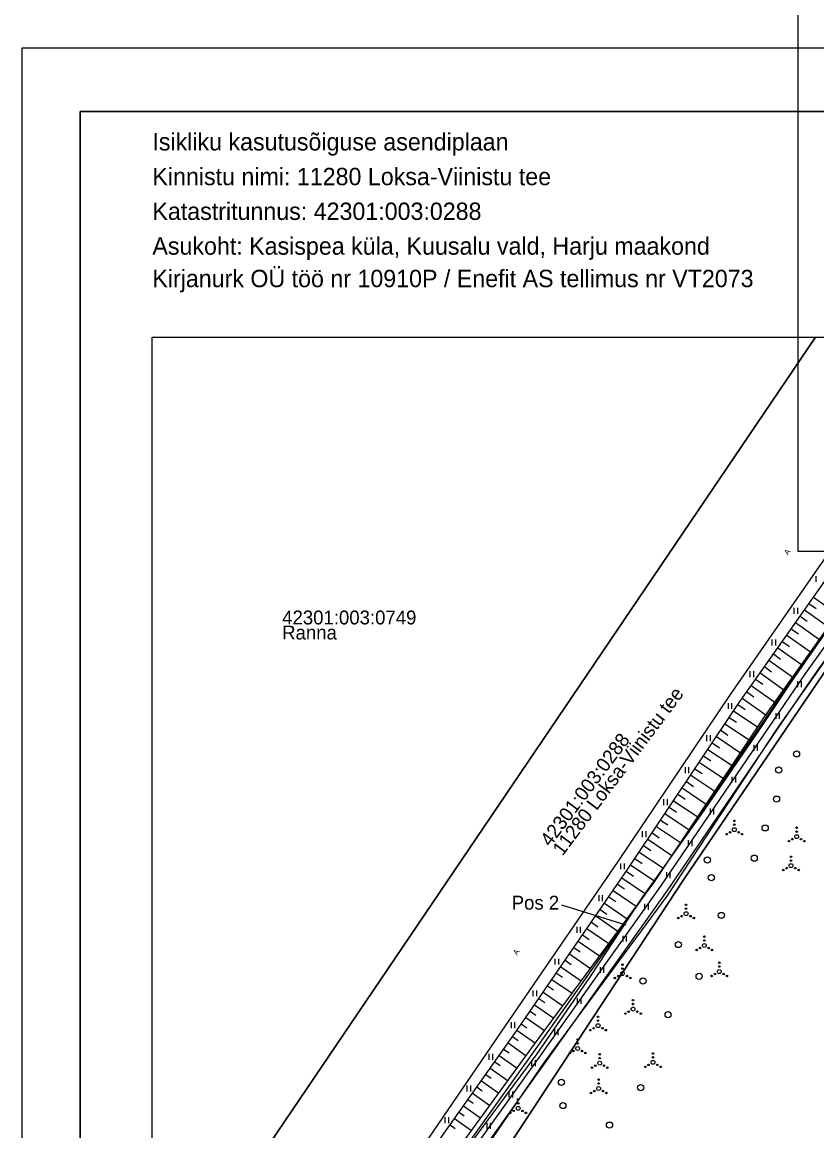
# Model space of a CAD drawing. Extents: x 599446 to 599962, y 6608194 to 6608886.
# Drawn here: x 599613.2 to 599716.2, y 6608430.8 to 6608574.4 of the extents above; entities that cross this region are included whole.
import ezdxf

# ---------------------------------------------------------------- set-up
doc = ezdxf.new("R2010")
doc.units = 0
for name, color, linetype in [('HALJASTUS', 7, 'Continuous'), ('KASUTUSALA', 7, 'Continuous'), ('MPKAABEL', 7, 'Continuous'), ('PIIR', 7, 'Continuous'), ('PR_SIDE', 7, 'Continuous'), ('RELJEEF', 7, 'Continuous'), ('TEE', 7, 'Continuous'), ('VORMISTUS_1', 7, 'Continuous'), ('VORMISTUS_2', 7, 'Continuous')]:
    doc.layers.add(name, color=color, linetype=linetype)

msp = doc.modelspace()

# ---------------------------------------------------------------- linework, layer by layer
at = {"layer": 'HALJASTUS'}
for p, q in [((599716.11, 6608502.67), (599716.11, 6608501.91)), ((599713.26, 6608498.56), (599713.26, 6608497.8)), ((599713.72, 6608498.56), (599713.72, 6608497.8)), ((599710.41, 6608494.45), (599710.41, 6608493.69)), ((599710.87, 6608494.45), (599710.87, 6608493.69)), ((599707.56, 6608490.34), (599707.56, 6608489.58)), ((599708.02, 6608490.34), (599708.02, 6608489.58)), ((599713.74, 6608489.04), (599713.74, 6608488.28)), ((599714.2, 6608489.04), (599714.2, 6608488.28)), ((599704.74, 6608486.22), (599704.74, 6608485.46)), ((599705.19, 6608486.22), (599705.19, 6608485.46)), ((599710.91, 6608484.92), (599710.91, 6608484.16)), ((599711.37, 6608484.92), (599711.37, 6608484.16)), ((599701.95, 6608482.07), (599701.95, 6608481.3)), ((599702.41, 6608482.07), (599702.41, 6608481.3)), ((599708.08, 6608480.8), (599708.08, 6608480.04)), ((599708.53, 6608480.8), (599708.53, 6608480.04)), ((599699.17, 6608477.91), (599699.17, 6608477.15)), ((599699.62, 6608477.91), (599699.62, 6608477.15)), ((599705.24, 6608476.68), (599705.24, 6608475.92)), ((599705.7, 6608476.68), (599705.7, 6608475.92)), ((599696.38, 6608473.76), (599696.38, 6608473)), ((599696.84, 6608473.76), (599696.84, 6608473)), ((599702.41, 6608472.57), (599702.41, 6608471.8)), ((599702.87, 6608472.57), (599702.87, 6608471.8)), ((599693.6, 6608469.61), (599693.6, 6608468.84)), ((599694.06, 6608469.61), (599694.06, 6608468.84)), ((599699.58, 6608468.45), (599699.58, 6608467.68)), ((599700.03, 6608468.45), (599700.03, 6608467.68)), ((599690.81, 6608465.46), (599690.81, 6608464.7)), ((599691.26, 6608465.46), (599691.26, 6608464.7)), ((599696.75, 6608464.33), (599696.75, 6608463.56)), ((599697.2, 6608464.33), (599697.2, 6608463.56)), ((599687.97, 6608461.34), (599687.97, 6608460.58)), ((599688.42, 6608461.34), (599688.42, 6608460.58)), ((599693.91, 6608460.21), (599693.91, 6608459.44)), ((599694.37, 6608460.21), (599694.37, 6608459.44)), ((599685.13, 6608457.23), (599685.13, 6608456.47)), ((599685.58, 6608457.23), (599685.58, 6608456.47)), ((599691.08, 6608456.09), (599691.08, 6608455.33)), ((599691.53, 6608456.09), (599691.53, 6608455.33)), ((599682.29, 6608453.11), (599682.29, 6608452.35)), ((599682.74, 6608453.11), (599682.74, 6608452.35)), ((599688.15, 6608452.03), (599688.15, 6608451.27)), ((599688.6, 6608452.03), (599688.6, 6608451.27)), ((599679.45, 6608449), (599679.45, 6608448.24)), ((599679.91, 6608449), (599679.91, 6608448.24)), ((599685.19, 6608448.01), (599685.19, 6608447.25)), ((599685.64, 6608448.01), (599685.64, 6608447.25)), ((599676.61, 6608444.88), (599676.61, 6608444.12)), ((599677.06, 6608444.88), (599677.06, 6608444.12)), ((599682.23, 6608443.98), (599682.23, 6608443.22)), ((599682.68, 6608443.98), (599682.68, 6608443.22)), ((599673.75, 6608440.78), (599673.75, 6608440.02)), ((599674.2, 6608440.78), (599674.2, 6608440.02)), ((599679.26, 6608439.95), (599679.26, 6608439.19)), ((599679.72, 6608439.95), (599679.72, 6608439.19)), ((599670.89, 6608436.68), (599670.89, 6608435.92)), ((599671.34, 6608436.68), (599671.34, 6608435.92)), ((599676.34, 6608435.9), (599676.34, 6608435.14)), ((599676.79, 6608435.9), (599676.79, 6608435.14)), ((599668.03, 6608432.58), (599668.03, 6608431.82)), ((599668.49, 6608432.58), (599668.49, 6608431.82)), ((599673.46, 6608431.81), (599673.46, 6608431.05)), ((599673.91, 6608431.81), (599673.91, 6608431.05))]:
    msp.add_line(p, q, dxfattribs=at)
msp.add_lwpolyline([(599677.55, 6608411.8), (599667.89, 6608408.84), (599664.05, 6608407.91), (599661.03, 6608410.48), (599668.3, 6608421.18), (599680.96, 6608439.71), (599696.95, 6608461.33), (599711.02, 6608482.75), (599725.24, 6608502.94), (599738.38, 6608523.58), (599745.5, 6608533.61)], dxfattribs=at)
for centre, radius in [((599713.62, 6608479.64), 0.4), ((599711.3, 6608477.55), 0.4), ((599711.02, 6608473.78), 0.4), ((599705.55, 6608470.97), 0.1), ((599704.98, 6608469.49), 0.1), ((599705.55, 6608469.82), 0.25), ((599705.55, 6608470.47), 0.1), ((599706.11, 6608469.49), 0.1), ((599709.55, 6608470.05), 0.4), ((599713.63, 6608470.07), 0.1), ((599713.63, 6608469.57), 0.1), ((599704.55, 6608469.24), 0.1), ((599706.55, 6608469.24), 0.1), ((599712.63, 6608468.34), 0.1), ((599713.07, 6608468.59), 0.1), ((599713.63, 6608468.92), 0.25), ((599714.2, 6608468.59), 0.1), ((599714.63, 6608468.34), 0.1), ((599702.06, 6608465.9), 0.4), ((599708.13, 6608466.13), 0.4), ((599712.9, 6608465.16), 0.25), ((599712.9, 6608466.31), 0.1), ((599712.9, 6608465.81), 0.1), ((599702.58, 6608463.6), 0.4), ((599711.9, 6608464.59), 0.1), ((599712.33, 6608464.84), 0.1), ((599713.46, 6608464.84), 0.1), ((599713.9, 6608464.59), 0.1), ((599699.3, 6608460.09), 0.1), ((599699.3, 6608459.59), 0.1), ((599698.3, 6608458.37), 0.1), ((599698.74, 6608458.62), 0.1), ((599699.3, 6608458.94), 0.25), ((599699.87, 6608458.62), 0.1), ((599700.3, 6608458.37), 0.1), ((599703.87, 6608458.71), 0.4), ((599698.31, 6608454.94), 0.4), ((599701.67, 6608455.97), 0.1), ((599701.67, 6608455.47), 0.1), ((599700.67, 6608454.24), 0.1), ((599701.11, 6608454.49), 0.1), ((599701.67, 6608454.82), 0.25), ((599702.24, 6608454.49), 0.1), ((599702.67, 6608454.24), 0.1), ((599691.06, 6608452.33), 0.1), ((599703.6, 6608452.59), 0.1), ((599690.5, 6608450.86), 0.1), ((599691.06, 6608451.18), 0.25), ((599691.06, 6608451.83), 0.1), ((599691.63, 6608450.86), 0.1), ((599700.99, 6608450.82), 0.4), ((599702.6, 6608450.87), 0.1), ((599703.04, 6608451.12), 0.1), ((599703.6, 6608451.44), 0.25), ((599703.6, 6608452.09), 0.1), ((599704.17, 6608451.12), 0.1), ((599704.6, 6608450.87), 0.1), ((599690.06, 6608450.61), 0.1), ((599692.06, 6608450.61), 0.1), ((599693.71, 6608450.21), 0.4), ((599692.43, 6608446.58), 0.25), ((599692.43, 6608447.73), 0.1), ((599692.43, 6608447.23), 0.1), ((599687.89, 6608445.58), 0.1), ((599687.89, 6608445.08), 0.1), ((599691.43, 6608446), 0.1), ((599691.86, 6608446.25), 0.1), ((599692.99, 6608446.25), 0.1), ((599693.43, 6608446), 0.1), ((599696.97, 6608445.86), 0.4), ((599686.89, 6608443.85), 0.1), ((599687.33, 6608444.1), 0.1), ((599687.89, 6608444.43), 0.25), ((599688.46, 6608444.1), 0.1), ((599688.89, 6608443.85), 0.1), ((599685.24, 6608442.62), 0.1), ((599685.24, 6608442.12), 0.1), ((599684.24, 6608440.89), 0.1), ((599684.68, 6608441.14), 0.1), ((599685.24, 6608441.47), 0.25), ((599685.81, 6608441.14), 0.1), ((599686.24, 6608440.89), 0.1), ((599688.1, 6608440.72), 0.1), ((599695, 6608440.83), 0.1), ((599687.53, 6608439.24), 0.1), ((599688.1, 6608439.57), 0.25), ((599688.1, 6608440.22), 0.1), ((599688.66, 6608439.24), 0.1), ((599694.43, 6608439.35), 0.1), ((599695, 6608439.68), 0.25), ((599695, 6608440.33), 0.1), ((599695.56, 6608439.35), 0.1), ((599687.1, 6608438.99), 0.1), ((599689.1, 6608438.99), 0.1), ((599694, 6608439.1), 0.1), ((599696, 6608439.1), 0.1), ((599683.14, 6608437.1), 0.4), ((599687.96, 6608436.29), 0.25), ((599687.96, 6608437.44), 0.1), ((599687.96, 6608436.94), 0.1), ((599693.41, 6608436.39), 0.4), ((599686.96, 6608435.71), 0.1), ((599687.4, 6608435.96), 0.1), ((599688.53, 6608435.96), 0.1), ((599688.96, 6608435.71), 0.1), ((599677.53, 6608433.72), 0.25), ((599677.53, 6608434.87), 0.1), ((599677.53, 6608434.37), 0.1), ((599683.33, 6608434.08), 0.4), ((599676.53, 6608433.14), 0.1), ((599676.96, 6608433.39), 0.1), ((599678.09, 6608433.39), 0.1), ((599678.53, 6608433.14), 0.1), ((599689.37, 6608431.55), 0.4)]:
    msp.add_circle(centre, radius, dxfattribs=at)
at = {"layer": 'KASUTUSALA'}
for points in [[(599664.6, 6608420.14), (599679.58, 6608441.05), (599695.18, 6608463.08), (599714.02, 6608490.66), (599723.56, 6608504.02), (599729.67, 6608515.64), (599742.57, 6608533.81), (599749.11, 6608542.06), (599759.78, 6608557.98), (599766.81, 6608568.23), (599773.98, 6608577.74), (599779.71, 6608585.87), (599791.27, 6608602.69), (599792.26, 6608607.28), (599805.5, 6608627.57), (599816.14, 6608643.34), (599826.26, 6608657.95), (599831.93, 6608665.81)], [(599833.56, 6608664.66), (599827.9, 6608656.79), (599817.79, 6608642.21), (599807.17, 6608626.46), (599794.14, 6608606.49), (599793.14, 6608601.88), (599784.35, 6608589.09), (599785.08, 6608589.36), (599783.13, 6608586.52), (599783.01, 6608586.48), (599781.3, 6608584.67), (599775.61, 6608576.57), (599768.44, 6608567.06), (599761.44, 6608556.85), (599750.73, 6608540.88), (599744.17, 6608532.61), (599731.38, 6608514.59), (599725.26, 6608502.97), (599715.66, 6608489.51), (599696.83, 6608461.94), (599681.21, 6608439.9), (599666.29, 6608419.07)]]:
    msp.add_lwpolyline(points, dxfattribs=at)
at = {"layer": 'MPKAABEL'}
msp.add_lwpolyline([(599648.76, 6608393.36), (599648.9, 6608393.53), (599653.62, 6608398.23), (599655.13, 6608401.84), (599657.09, 6608405.45), (599661.77, 6608414.04), (599664.74, 6608420.07), (599671.51, 6608429.39), (599679.99, 6608440.77), (599686.92, 6608450.81), (599693.7, 6608461.11), (599700.88, 6608471.17), (599708.65, 6608482.49), (599713.04, 6608489.11), (599720.19, 6608499.33), (599726.29, 6608507.65), (599730.94, 6608514.83), (599737.34, 6608523.47), (599743.77, 6608532.91), (599744.32, 6608533.61)], dxfattribs=at)
at = {"layer": 'PIIR'}
for points in [[(599716.08, 6608533.61), (599630.11, 6608406.68)], [(599630.11, 6608406.68), (599716.08, 6608533.61)], [(599746.81, 6608533.61), (599736.72, 6608518.91), (599698.98, 6608463.34), (599658.83, 6608402.26), (599640.26, 6608376.11)], [(599640.37, 6608376.11), (599658.83, 6608402.26), (599698.98, 6608463.34), (599736.72, 6608518.91), (599753.86, 6608515.91)]]:
    msp.add_lwpolyline(points, dxfattribs=at)
at = {"layer": 'PR_SIDE'}
msp.add_lwpolyline([(599666.23, 6608401.55), (599662.07, 6608402.56), (599660.26, 6608402.27), (599659.38, 6608402.48), (599659.32, 6608407.89), (599659.48, 6608408.77), (599665.44, 6608419.61), (599680.4, 6608440.48), (599696.01, 6608462.51), (599714.84, 6608490.08), (599724.41, 6608503.49), (599730.53, 6608515.12), (599743.37, 6608533.21), (599749.92, 6608541.47), (599760.61, 6608557.42), (599767.63, 6608567.64), (599774.8, 6608577.16), (599780.53, 6608585.3)], dxfattribs=at)
at = {"layer": 'RELJEEF'}
for p, q in [((599715.81, 6608499.93), (599718.92, 6608497.73)), ((599714.65, 6608498.3), (599717.76, 6608496.1)), ((599715.23, 6608499.11), (599716.16, 6608498.46)), ((599714.08, 6608497.48), (599715.01, 6608496.82)), ((599712.93, 6608495.84), (599713.85, 6608495.19)), ((599713.5, 6608496.66), (599716.6, 6608494.47)), ((599711.77, 6608494.21), (599712.7, 6608493.56)), ((599712.35, 6608495.03), (599715.44, 6608492.84)), ((599710.62, 6608492.58), (599711.55, 6608491.92)), ((599711.2, 6608493.39), (599714.28, 6608491.21)), ((599710.04, 6608491.76), (599713.13, 6608489.58)), ((599708.89, 6608490.12), (599711.97, 6608487.95)), ((599709.47, 6608490.94), (599710.39, 6608490.29)), ((599707.74, 6608488.49), (599710.81, 6608486.32)), ((599708.31, 6608489.31), (599709.24, 6608488.66)), ((599706.58, 6608486.86), (599709.65, 6608484.69)), ((599707.16, 6608487.67), (599708.08, 6608487.02)), ((599706.01, 6608486.04), (599706.95, 6608485.41)), ((599704.9, 6608484.37), (599705.84, 6608483.75)), ((599705.46, 6608485.21), (599708.58, 6608483.11)), ((599703.79, 6608482.71), (599704.73, 6608482.08)), ((599704.34, 6608483.54), (599707.47, 6608481.45)), ((599702.68, 6608481.05), (599703.61, 6608480.42)), ((599703.23, 6608481.88), (599706.36, 6608479.79)), ((599702.12, 6608480.22), (599705.25, 6608478.13)), ((599701.01, 6608478.56), (599704.13, 6608476.46)), ((599701.56, 6608479.39), (599702.5, 6608478.76)), ((599699.9, 6608476.89), (599703.02, 6608474.8)), ((599700.45, 6608477.72), (599701.39, 6608477.1)), ((599698.78, 6608475.23), (599701.91, 6608473.14)), ((599699.34, 6608476.06), (599700.28, 6608475.43)), ((599698.23, 6608474.4), (599699.17, 6608473.77)), ((599697.12, 6608472.74), (599698.05, 6608472.11)), ((599697.67, 6608473.57), (599700.8, 6608471.48)), ((599696, 6608471.07), (599696.94, 6608470.45)), ((599696.56, 6608471.91), (599699.69, 6608469.81)), ((599695.45, 6608470.24), (599698.58, 6608468.15)), ((599694.34, 6608468.58), (599697.46, 6608466.49)), ((599694.89, 6608469.41), (599695.83, 6608468.78)), ((599693.23, 6608466.92), (599696.35, 6608464.83)), ((599693.78, 6608467.75), (599694.72, 6608467.12)), ((599692.11, 6608465.26), (599695.24, 6608463.16)), ((599692.67, 6608466.09), (599693.61, 6608465.46)), ((599691.55, 6608464.43), (599692.47, 6608463.79)), ((599690.42, 6608462.78), (599691.32, 6608462.16)), ((599690.99, 6608463.6), (599694.03, 6608461.51)), ((599689.28, 6608461.13), (599690.17, 6608460.52)), ((599689.85, 6608461.96), (599692.84, 6608459.9)), ((599688.15, 6608459.49), (599689.02, 6608458.89)), ((599688.72, 6608460.31), (599691.65, 6608458.29)), ((599687.58, 6608458.66), (599690.46, 6608456.68)), ((599686.45, 6608457.02), (599689.28, 6608455.07)), ((599687.02, 6608457.84), (599687.87, 6608457.25)), ((599685.31, 6608455.37), (599688.09, 6608453.46)), ((599685.88, 6608456.19), (599686.72, 6608455.61)), ((599684.18, 6608453.72), (599686.9, 6608451.85)), ((599684.75, 6608454.54), (599685.57, 6608453.98)), ((599683.61, 6608452.9), (599684.42, 6608452.34)), ((599682.48, 6608451.25), (599683.27, 6608450.7)), ((599683.05, 6608452.07), (599685.71, 6608450.24)), ((599681.34, 6608449.6), (599682.12, 6608449.07)), ((599681.91, 6608450.43), (599684.53, 6608448.63)), ((599680.21, 6608447.96), (599680.97, 6608447.43)), ((599680.78, 6608448.78), (599683.34, 6608447.01)), ((599679.64, 6608447.13), (599682.15, 6608445.4)), ((599678.51, 6608445.48), (599680.96, 6608443.79)), ((599679.08, 6608446.31), (599679.82, 6608445.8)), ((599677.37, 6608443.84), (599679.78, 6608442.18)), ((599677.94, 6608444.66), (599678.67, 6608444.16)), ((599676.22, 6608442.2), (599678.57, 6608440.54)), ((599676.8, 6608443.02), (599677.51, 6608442.52)), ((599675.65, 6608441.38), (599676.35, 6608440.89)), ((599674.49, 6608439.75), (599675.19, 6608439.26)), ((599675.07, 6608440.57), (599677.4, 6608438.92)), ((599673.33, 6608438.12), (599674.02, 6608437.63)), ((599673.91, 6608438.94), (599676.22, 6608437.3)), ((599672.18, 6608436.49), (599672.86, 6608436.01)), ((599672.76, 6608437.3), (599675.04, 6608435.69)), ((599671.6, 6608435.67), (599673.86, 6608434.07)), ((599670.45, 6608434.04), (599672.68, 6608432.46)), ((599671.02, 6608434.86), (599671.7, 6608434.38)), ((599669.29, 6608432.41), (599671.5, 6608430.84)), ((599669.87, 6608433.22), (599670.53, 6608432.75)), ((599668.71, 6608431.59), (599669.37, 6608431.12))]:
    msp.add_line(p, q, dxfattribs=at)
for points in [[(599654.69, 6608405.38), (599653.52, 6608406.01), (599653.02, 6608406.94), (599663.76, 6608424.59), (599677.05, 6608443.37), (599691.81, 6608464.8), (599706.09, 6608486.16), (599720.4, 6608506.43), (599733.78, 6608526.84), (599738.5, 6608533.61)], [(599663.44, 6608407.21), (599660.22, 6608406.81), (599655.45, 6608405.61), (599654.97, 6608406.29), (599665.97, 6608423.26), (599679.67, 6608442.04), (599695.19, 6608463.08), (599709.47, 6608484.45), (599723.46, 6608504.12), (599736.95, 6608524.13), (599743.91, 6608533.61)]]:
    msp.add_lwpolyline(points, dxfattribs=at)
at = {"layer": 'TEE'}
msp.add_lwpolyline([(599736.47, 6608533.61), (599732.82, 6608528.11), (599719.27, 6608507.84), (599705, 6608487.33), (599690.45, 6608465.68), (599675.86, 6608444.39), (599662.84, 6608425.37), (599650.3, 6608406.72), (599646.9, 6608401.43), (599645.55, 6608399.88)], dxfattribs=at)
at = {"layer": 'VORMISTUS_1'}
msp.add_line((599691.53, 6608457.45), (599683.18, 6608460.05), dxfattribs=at)
for points in [[(599613.24, 6608571.11), (599770.74, 6608571.11), (599770.74, 6608348.36), (599613.24, 6608348.36)], [(599620.74, 6608356.61), (599763.24, 6608356.61), (599763.24, 6608562.86), (599620.74, 6608562.86)], [(599620.74, 6608562.86), (599763.24, 6608562.86), (599763.24, 6608356.61), (599620.74, 6608356.61)], [(599753.86, 6608376.11), (599630.11, 6608376.11), (599630.11, 6608533.61), (599753.86, 6608533.61)]]:
    msp.add_lwpolyline(points, close=True, dxfattribs=at)
at = {"layer": 'VORMISTUS_2'}
msp.add_lwpolyline([(599713.81, 6608728.61), (599871.31, 6608728.61), (599871.31, 6608505.86), (599713.81, 6608505.86)], close=True, dxfattribs=at)

# ---------------------------------------------------------------- texts
at = {"layer": 'PIIR'}
for s, p in [('42301:003:0749', (599646.94, 6608496.41)), ('Ranna', (599646.94, 6608494.46))]:
    msp.add_text(s, height=1.8, dxfattribs=at).set_placement(p)
for s, p in [('11280 Loksa-Viinistu tee', (599683.28, 6608466.32)), ('42301:003:0288', (599681.68, 6608467.52))]:
    msp.add_text(s, height=1.8, rotation=53.1604, dxfattribs=at).set_placement(p)
at = {"layer": 'TEE'}
for p in [(599712.5, 6608505.34), (599677.38, 6608453.5)]:
    msp.add_text('A', height=0.7, rotation=56.1404, dxfattribs=at).set_placement(p)
at = {"layer": 'VORMISTUS_1'}
for s, height, p in [('Isikliku kasutusõiguse asendiplaan', 2.25, (599630.12, 6608557.81)), ('Kinnistu nimi: 11280 Loksa-Viinistu tee', 2.25, (599630.12, 6608553.31)), ('Katastritunnus: 42301:003:0288', 2.25, (599630.12, 6608548.81)), ('Asukoht: Kasispea küla, Kuusalu vald, Harju maakond', 2.25, (599630.12, 6608544.31)), ('Pos 2', 1.8, (599676.69, 6608459.46))]:
    msp.add_text(s, height=height, dxfattribs=at).set_placement(p)
msp.add_text('Kirjanurk OÜ töö nr 10910P / Enefit AS tellimus nr VT2073', height=2.25, rotation=360, dxfattribs=at).set_placement((599630.11, 6608540.1))

doc.saveas('drawing.dxf')
